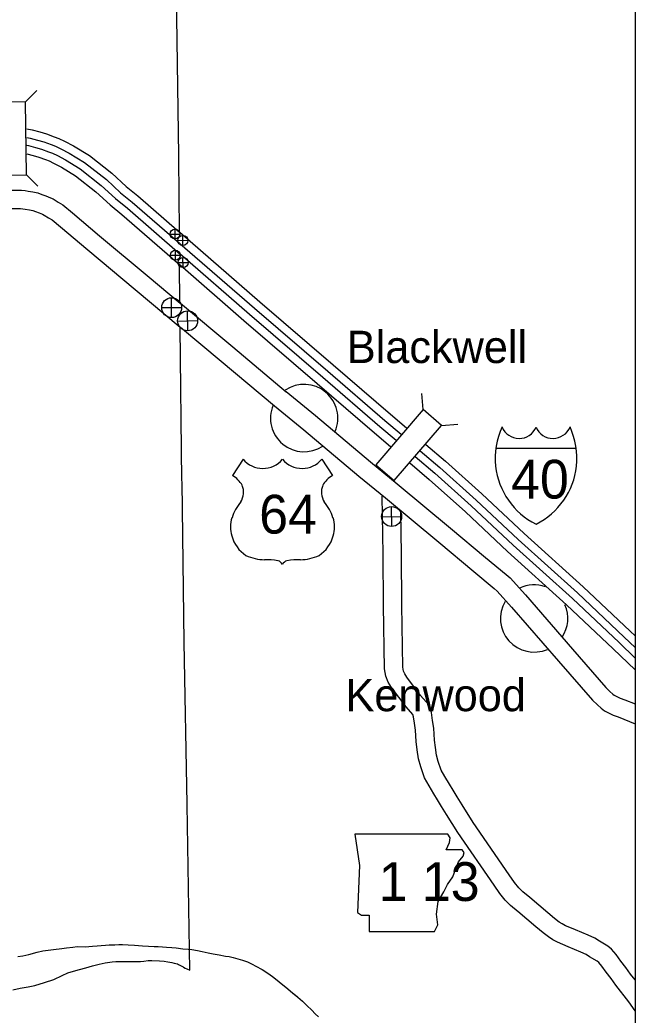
# Model space of a CAD drawing. Extents: x 1374139 to 1377472, y 1168351 to 1170484.
# Drawn here: x 1374928.1 to 1375028.5, y 1169859.1 to 1170021.6 of the extents above; entities that cross this region are included whole.
import ezdxf

# ---------------------------------------------------------------- set-up
doc = ezdxf.new("R2010")
doc.units = 0
doc.layers.add('26', color=7, linetype='Continuous')
doc.layers.add('Default', color=7, linetype='Continuous')

msp = doc.modelspace()

# ---------------------------------------------------------------- linework, layer by layer
at = {"layer": '26'}
msp.add_lwpolyline([(1374299.15, 1170388.77), (1375028.55, 1170388.77), (1375028.55, 1169604.28), (1374299.15, 1169604.28)], close=True, dxfattribs=at)
at = {"layer": 'Default'}
for p, q in [((1374929.05, 1170008.22), (1374930.9, 1170010.11)), ((1374929.19, 1169996.34), (1374931.08, 1169994.49)), ((1374952.64, 1169986.65), (1374954.27, 1169986.65)), ((1374953.45, 1169985.84), (1374953.45, 1169987.47)), ((1374954.75, 1169984.79), (1374954.71, 1169986.41)), ((1374953.92, 1169985.58), (1374955.54, 1169985.62)), ((1374952.7, 1169983.19), (1374954.33, 1169983.19)), ((1374953.51, 1169982.38), (1374953.51, 1169984.01)), ((1374953.96, 1169981.98), (1374955.58, 1169982.01)), ((1374954.79, 1169981.18), (1374954.75, 1169982.81)), ((1374952.9, 1169973), (1374952.9, 1169976.25)), ((1374951.28, 1169974.62), (1374954.53, 1169974.62)), ((1374955.55, 1169970.85), (1374955.48, 1169974.1)), ((1374953.89, 1169972.44), (1374957.14, 1169972.51)), ((1374993.95, 1169957.97), (1374993.75, 1169960.6)), ((1374993.95, 1169957.97), (1374986.22, 1169948.94)), ((1374996.96, 1169955.39), (1374993.95, 1169957.97)), ((1374989.23, 1169946.37), (1374996.96, 1169955.39)), ((1374996.96, 1169955.39), (1374999.59, 1169955.59)), ((1375005.83, 1169951.67), (1375018.94, 1169951.67)), ((1374964.56, 1169949.86), (1374962.83, 1169947.18)), ((1374977.43, 1169949.86), (1374979.16, 1169947.18)), ((1374986.22, 1169948.94), (1374989.23, 1169946.37)), ((1374988.85, 1169938.87), (1374988.77, 1169942.12)), ((1374987.18, 1169940.46), (1374990.44, 1169940.53)), ((1375011.37, 1169878.25), (1375011.35, 1169878.26)), ((1375009.43, 1169875.96), (1375009.45, 1169875.94))]:
    msp.add_line(p, q, dxfattribs=at)
for points in [[(1374954.06, 1169999.49), (1374953.67, 1170025.83), (1374953.65, 1170026.12), (1374953.46, 1170051.85), (1374953.45, 1170052.58), (1374953.18, 1170079.07), (1374953, 1170105.34), (1374952.99, 1170105.65), (1374952.81, 1170118.59)], [(1374929.26, 1170003.84), (1374930.14, 1170003.66), (1374931.39, 1170003.33), (1374932.5, 1170003.01), (1374933.72, 1170002.55), (1374934.46, 1170002.27), (1374935.43, 1170001.81), (1374936.88, 1170001.04), (1374939.49, 1169999.45), (1374943.13, 1169996.58), (1374945.46, 1169994.43), (1374947.36, 1169992.89), (1374954.18, 1169986.97)], [(1374929.24, 1170002.44), (1374929.83, 1170002.32), (1374931.02, 1170002), (1374932.06, 1170001.7), (1374933.24, 1170001.26), (1374933.92, 1170001.01), (1374934.81, 1170000.58), (1374936.2, 1169999.85), (1374938.7, 1169998.32), (1374942.24, 1169995.53), (1374944.56, 1169993.39), (1374946.47, 1169991.84), (1374954.16, 1169985.17)], [(1374929.29, 1170001.15), (1374929.54, 1170001.1), (1374930.69, 1170000.8), (1374931.67, 1170000.51), (1374932.8, 1170000.09), (1374933.44, 1169999.85), (1374934.25, 1169999.47), (1374935.59, 1169998.76), (1374937.99, 1169997.29), (1374941.42, 1169994.58), (1374943.74, 1169992.45), (1374945.67, 1169990.88), (1374954.31, 1169983.38)], [(1374929.29, 1169999.75), (1374930.32, 1169999.47), (1374931.23, 1169999.21), (1374932.32, 1169998.8), (1374932.9, 1169998.59), (1374933.63, 1169998.24), (1374934.9, 1169997.56), (1374937.2, 1169996.16), (1374940.53, 1169993.53), (1374942.84, 1169991.4), (1374944.79, 1169989.83), (1374954.22, 1169981.64)], [(1374954.17, 1169987.04), (1374954.07, 1169999.04), (1374954.06, 1169999.49)], [(1374923.05, 1169993.67), (1374925.75, 1169993.8), (1374927.44, 1169993.81), (1374928.39, 1169993.82), (1374929, 1169993.75), (1374929.5, 1169993.67), (1374930.25, 1169993.53), (1374931.04, 1169993.38), (1374931.72, 1169993.13), (1374932.37, 1169992.9), (1374933.13, 1169992.58), (1374933.54, 1169992.37), (1374934.37, 1169991.86), (1374935.15, 1169991.39), (1374936.7, 1169990.13), (1374941.15, 1169986.38), (1374948.89, 1169979.89), (1374954.3, 1169975.37)], [(1374923.2, 1169990.67), (1374925.83, 1169990.8), (1374927.46, 1169990.81), (1374928.23, 1169990.82), (1374928.6, 1169990.77), (1374929, 1169990.71), (1374929.69, 1169990.58), (1374930.23, 1169990.48), (1374930.7, 1169990.31), (1374931.29, 1169990.1), (1374931.84, 1169989.87), (1374932.07, 1169989.75), (1374932.82, 1169989.3), (1374933.41, 1169988.94), (1374934.78, 1169987.82), (1374939.22, 1169984.08), (1374946.97, 1169977.59), (1374954.3, 1169971.46)], [(1374954.23, 1169986.93), (1374967.32, 1169975.57)], [(1374954.23, 1169985.1), (1374966.42, 1169974.53)], [(1374954.24, 1169983.44), (1374965.6, 1169973.58)], [(1374954.26, 1169975.51), (1374954.21, 1169981.55)], [(1374954.27, 1169981.59), (1374964.7, 1169972.54)], [(1374954.32, 1169975.35), (1374962.89, 1169968.2), (1374971.62, 1169960.89)], [(1374967.31, 1169975.57), (1374979.27, 1169965.28), (1374988.62, 1169957.22), (1374991.23, 1169954.99)], [(1374965.6, 1169973.58), (1374977.56, 1169963.29), (1374986.91, 1169955.23), (1374989.53, 1169952.99)], [(1374966.41, 1169974.53), (1374978.38, 1169964.24), (1374987.72, 1169956.18), (1374990.34, 1169953.94)], [(1374964.7, 1169972.54), (1374976.66, 1169962.25), (1374986.01, 1169954.19), (1374988.62, 1169951.95)], [(1374955.85, 1169866.38), (1374955.44, 1169893.42), (1374955.41, 1169893.58), (1374954.93, 1169919.93), (1374954.64, 1169946.09), (1374954.58, 1169946.46), (1374954.29, 1169971.37)], [(1374954.33, 1169971.44), (1374960.97, 1169965.89), (1374969.69, 1169958.59)], [(1374971.61, 1169960.9), (1374976.38, 1169956.98), (1374985.37, 1169949.42), (1374989.73, 1169945.85), (1374998.42, 1169938.62), (1375004.15, 1169933.82), (1375007.48, 1169931.05), (1375008.15, 1169930.46), (1375010.64, 1169927.7), (1375018.32, 1169918.86), (1375023.76, 1169912.59), (1375024.45, 1169911.92), (1375024.93, 1169911.48), (1375025.15, 1169911.31), (1375026.12, 1169910.84), (1375026.85, 1169910.58), (1375028.55, 1169909.89)], [(1374969.7, 1169958.58), (1374974.47, 1169954.67), (1374983.45, 1169947.11), (1374987.82, 1169943.53), (1374996.5, 1169936.31), (1375002.23, 1169931.52), (1375005.54, 1169928.76), (1375006.05, 1169928.31), (1375008.39, 1169925.71), (1375016.05, 1169916.9), (1375021.58, 1169910.52), (1375022.4, 1169909.73), (1375022.99, 1169909.2), (1375023.54, 1169908.76), (1375024.95, 1169908.07), (1375025.78, 1169907.78), (1375028.55, 1169906.65)], [(1374994.38, 1169952.28), (1374997.59, 1169949.54), (1375003.56, 1169944.2), (1375010.42, 1169937.75), (1375020.1, 1169929.03), (1375027.74, 1169921.8), (1375028.55, 1169921.02)], [(1374993.49, 1169951.24), (1374996.68, 1169948.5), (1375002.63, 1169943.19), (1375009.49, 1169936.74), (1375019.16, 1169928.02), (1375026.79, 1169920.8), (1375028.55, 1169919.1)], [(1374991.76, 1169949.27), (1374994.96, 1169946.53), (1375000.86, 1169941.25), (1375007.71, 1169934.81), (1375017.38, 1169926.09), (1375024.98, 1169918.91), (1375028.55, 1169915.45)], [(1374992.67, 1169950.3), (1374995.86, 1169947.56), (1375001.79, 1169942.27), (1375008.65, 1169935.82), (1375018.31, 1169927.1), (1375025.93, 1169919.9), (1375028.55, 1169917.36)], [(1375009.45, 1169875.94), (1375008.21, 1169876.96), (1375007.34, 1169877.84), (1375006.47, 1169878.9), (1375005.54, 1169880.28), (1374999.61, 1169888.89), (1374997.78, 1169891.82), (1374996.94, 1169893.13), (1374996.28, 1169894.24), (1374995.68, 1169895.21), (1374994.91, 1169896.52), (1374994.18, 1169897.82), (1374993.55, 1169899.62), (1374993.21, 1169900.92), (1374992.97, 1169902.37), (1374992.83, 1169903.73), (1374992.73, 1169905.59), (1374992.52, 1169906.74), (1374992.38, 1169907.8), (1374992.25, 1169908.18), (1374991.18, 1169909.39), (1374988.79, 1169912.55), (1374988.25, 1169913.45), (1374987.87, 1169914.4), (1374987.66, 1169915.61), (1374987.49, 1169925.98), (1374987.44, 1169934.33), (1374987.29, 1169943.84)], [(1375011.35, 1169878.26), (1375010.23, 1169879.18), (1375009.57, 1169879.85), (1375008.89, 1169880.69), (1375008.02, 1169881.97), (1375002.12, 1169890.53), (1375000.31, 1169893.43), (1374999.5, 1169894.7), (1374998.85, 1169895.8), (1374998.25, 1169896.76), (1374997.51, 1169898.01), (1374996.92, 1169899.06), (1374996.42, 1169900.5), (1374996.14, 1169901.54), (1374995.95, 1169902.76), (1374995.83, 1169903.96), (1374995.72, 1169905.95), (1374995.48, 1169907.2), (1374995.32, 1169908.49), (1374994.89, 1169909.72), (1374993.51, 1169911.29), (1374991.28, 1169914.24), (1374990.94, 1169914.8), (1374990.77, 1169915.22), (1374990.65, 1169915.89), (1374990.49, 1169926.02), (1374990.44, 1169934.37), (1374990.33, 1169941.37)], [(1375028.55, 1169864.8), (1375027.82, 1169865.77), (1375027.02, 1169866.85), (1375026.25, 1169867.85), (1375025.48, 1169868.94), (1375024.68, 1169869.81), (1375024.08, 1169870.31), (1375022.72, 1169871.13), (1375022, 1169871.62), (1375020.89, 1169872.09), (1375018.8, 1169872.99), (1375017.89, 1169873.35), (1375017.17, 1169873.66), (1375016.65, 1169873.94), (1375016.15, 1169874.26), (1375015.42, 1169874.85), (1375014.29, 1169875.78), (1375011.37, 1169878.25)], [(1375028.55, 1169859.77), (1375027.51, 1169861.2), (1375025.41, 1169863.97), (1375024.62, 1169865.04), (1375023.83, 1169866.07), (1375023.13, 1169867.06), (1375022.61, 1169867.63), (1375022.34, 1169867.85), (1375021.1, 1169868.6), (1375020.55, 1169868.98), (1375019.71, 1169869.34), (1375017.65, 1169870.22), (1375016.73, 1169870.59), (1375015.87, 1169870.96), (1375015.13, 1169871.35), (1375014.4, 1169871.83), (1375013.53, 1169872.51), (1375012.36, 1169873.47), (1375009.43, 1169875.96)], [(1374927.8, 1169868.64), (1374928.61, 1169868.72), (1374929.6, 1169868.97), (1374930.93, 1169869.34), (1374931.88, 1169869.53), (1374932.72, 1169869.66), (1374933.61, 1169869.76), (1374934.96, 1169869.96), (1374935.74, 1169870.03), (1374936.76, 1169870.15), (1374937.5, 1169870.24), (1374938.91, 1169870.23), (1374939.39, 1169870.27), (1374940, 1169870.32), (1374940.72, 1169870.38), (1374941.42, 1169870.44), (1374942.1, 1169870.5), (1374942.69, 1169870.55), (1374943.61, 1169870.56), (1374944.26, 1169870.58), (1374944.89, 1169870.58), (1374945.78, 1169870.54), (1374946.84, 1169870.47), (1374948.15, 1169870.36), (1374949.14, 1169870.31), (1374950.05, 1169870.26), (1374950.69, 1169870.24), (1374951.4, 1169870.22), (1374952.08, 1169870.18), (1374952.92, 1169870.09), (1374953.64, 1169870.03), (1374954.72, 1169869.9), (1374955.58, 1169869.81), (1374956.19, 1169869.75), (1374957.12, 1169869.61), (1374957.89, 1169869.47), (1374958.86, 1169869.25), (1374959.7, 1169869.08), (1374960.68, 1169868.88), (1374961.71, 1169868.7), (1374962.31, 1169868.61), (1374962.95, 1169868.48), (1374963.71, 1169868.26), (1374964.49, 1169868.02), (1374965.26, 1169867.74), (1374966.03, 1169867.38), (1374966.66, 1169867.06), (1374967.67, 1169866.51), (1374968.58, 1169865.91), (1374969.34, 1169865.36), (1374970.12, 1169864.75), (1374970.79, 1169864.21), (1374971.52, 1169863.63), (1374972.62, 1169862.72), (1374973.39, 1169862.1)], [(1374927.8, 1169868.64), (1374928.61, 1169868.72), (1374929.6, 1169868.97), (1374930.93, 1169869.34), (1374931.88, 1169869.53), (1374932.72, 1169869.66), (1374933.61, 1169869.76), (1374934.96, 1169869.96), (1374935.74, 1169870.03), (1374936.76, 1169870.15), (1374937.5, 1169870.24), (1374938.91, 1169870.23), (1374939.39, 1169870.27), (1374940, 1169870.32), (1374940.72, 1169870.38), (1374941.42, 1169870.44), (1374942.1, 1169870.5), (1374942.69, 1169870.55), (1374943.61, 1169870.56), (1374944.26, 1169870.58), (1374944.89, 1169870.58), (1374945.78, 1169870.54), (1374946.84, 1169870.47), (1374948.15, 1169870.36), (1374949.14, 1169870.31), (1374950.05, 1169870.26), (1374950.69, 1169870.24), (1374951.4, 1169870.22), (1374952.08, 1169870.18), (1374952.92, 1169870.09), (1374953.64, 1169870.03), (1374954.72, 1169869.9), (1374955.58, 1169869.81), (1374956.19, 1169869.75), (1374957.12, 1169869.61), (1374957.89, 1169869.47), (1374958.86, 1169869.25), (1374959.7, 1169869.08), (1374960.68, 1169868.88), (1374961.71, 1169868.7), (1374962.31, 1169868.61), (1374962.95, 1169868.48), (1374963.71, 1169868.26), (1374964.49, 1169868.02), (1374965.26, 1169867.74), (1374966.03, 1169867.38), (1374966.66, 1169867.06), (1374967.67, 1169866.51), (1374968.58, 1169865.91), (1374969.34, 1169865.36), (1374970.12, 1169864.75), (1374970.79, 1169864.21), (1374971.52, 1169863.63), (1374972.62, 1169862.72), (1374973.52, 1169862), (1374974.24, 1169861.34), (1374974.97, 1169860.64), (1374975.76, 1169859.88), (1374976.34, 1169859.27), (1374976.88, 1169858.75)], [(1374926.99, 1169863.16), (1374928.19, 1169863.43), (1374929.46, 1169863.68), (1374930.57, 1169863.88), (1374932.15, 1169864.39), (1374933.65, 1169864.88), (1374935.02, 1169865.5), (1374935.94, 1169865.97), (1374936.86, 1169866.25), (1374937.84, 1169866.51), (1374938.87, 1169866.79), (1374939.99, 1169867.08), (1374941.05, 1169867.35), (1374942.07, 1169867.58), (1374943.17, 1169867.75), (1374943.78, 1169867.82), (1374945.04, 1169867.83), (1374946.13, 1169867.8), (1374946.98, 1169867.82), (1374947.8, 1169867.83), (1374948.36, 1169867.87), (1374949.09, 1169867.97), (1374949.69, 1169868), (1374950.91, 1169867.94), (1374951.68, 1169867.85), (1374952.3, 1169867.74), (1374952.93, 1169867.63), (1374953.31, 1169867.55), (1374953.83, 1169867.42), (1374954.03, 1169867.34), (1374954.8, 1169866.92), (1374954.86, 1169866.88), (1374955.1, 1169866.75), (1374955.38, 1169866.61), (1374955.85, 1169866.38)]]:
    msp.add_lwpolyline(points, dxfattribs=at)
for points in [[(1374925.09, 1170008.17), (1374925.23, 1169996.29), (1374929.19, 1169996.34), (1374929.05, 1170008.22)], [(1374982.8, 1169888.6), (1374983.56, 1169883.52), (1374983.22, 1169875.82), (1374983.9, 1169875.4), (1374985.17, 1169875.4), (1374985.17, 1169872.69), (1374995.82, 1169872.69), (1374996.33, 1169873.79), (1374996.16, 1169875.57), (1374996.42, 1169877.6), (1374997.35, 1169879.21), (1374997.94, 1169880.39), (1374998.79, 1169881.66), (1374999.29, 1169883.01), (1374999.72, 1169884.11), (1375000.48, 1169885.04), (1375000.65, 1169885.64), (1375000.31, 1169886.06), (1374997.69, 1169886.06), (1374998.28, 1169887.24), (1374998.36, 1169888), (1374998.01, 1169888.59)]]:
    msp.add_lwpolyline(points, close=True, dxfattribs=at)
for centre, radius in [((1374953.45, 1169986.65), 0.812), ((1374954.73, 1169985.6), 0.814), ((1374953.51, 1169983.19), 0.812), ((1374954.77, 1169982), 0.814), ((1374952.9, 1169974.62), 1.62), ((1374955.51, 1169972.47), 1.63), ((1374988.81, 1169940.5), 1.63)]:
    msp.add_circle(centre, radius, dxfattribs=at)
for centre, radius, start, end in [((1374974.53, 1169956.58), 5.5, 336.6912, 124.0772), ((1374974.53, 1169956.58), 5.5, 157.5294, 303.4574), ((1375018.01, 1169949.97), 12.3, 155.2204, 185.7928), ((1375009.62, 1169956.25), 3, 202.1459, 337.3414), ((1375015.15, 1169956.25), 3, 202.6586, 337.8541), ((1375006.76, 1169949.97), 12.3, 354.2072, 24.7796), ((1374967.78, 1169952.57), 4.21, 220.075, 319.6701), ((1374974.21, 1169952.57), 4.21, 220.3299, 319.925), ((1375017.79, 1169950.07), 12.09, 186.3923, 243.4571), ((1375006.98, 1169950.07), 12.09, 296.5429, 353.6077), ((1374960.57, 1169943.3), 4.5, 30.7809, 59.9883), ((1374981.42, 1169943.3), 4.5, 120.0117, 149.2191), ((1374961.56, 1169944.48), 3.08, 328.8105, 21.2108), ((1374980.43, 1169944.48), 3.08, 158.7892, 211.1895), ((1374969.62, 1169938.17), 7.19, 138.9565, 162.6913), ((1374972.37, 1169938.17), 7.19, 17.3087, 41.0435), ((1374967.24, 1169938.76), 4.75, 160.9576, 197.3819), ((1374974.75, 1169938.76), 4.75, 342.6181, 19.0424), ((1374968.02, 1169938.77), 5.5, 195.1074, 237.1312), ((1374973.97, 1169938.77), 5.5, 302.8688, 344.8926), ((1374968.12, 1169940.5), 7.06, 244.0771, 269.5779), ((1374968.28, 1169920.51), 12.93, 81.1942, 90.9539), ((1374969.9, 1169932.1), 1.24, 28.0342, 72.9864), ((1374972.09, 1169932.1), 1.24, 107.0136, 151.9658), ((1374973.71, 1169920.51), 12.93, 89.0461, 98.8058), ((1374973.87, 1169940.5), 7.06, 270.4221, 295.9229), ((1375012.07, 1169923.85), 5.5, 70.4975, 115.5599), ((1375012.07, 1169923.85), 5.5, 149.7035, 293.2729), ((1375012.07, 1169923.85), 5.5, 326.1547, 23.7908)]:
    msp.add_arc(centre, radius, start, end, dxfattribs=at)

# ---------------------------------------------------------------- texts
for s, height, p in [('Blackwell', 5.28, (1374981.5, 1169965.57)), ('40', 6.336, (1375008.31, 1169943.43)), ('64', 6.336, (1374967.19, 1169937.71)), ('Kenwood', 5.28, (1374981.28, 1169908.7)), ('1 13', 6.336, (1374986.68, 1169877.7))]:
    msp.add_text(s, height=height, dxfattribs=at).set_placement(p)

doc.saveas('drawing.dxf')
